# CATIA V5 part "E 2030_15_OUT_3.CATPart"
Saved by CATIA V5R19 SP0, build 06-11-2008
Material "Plastic": density 1200 kg/m3, Young's modulus 2.2e+09 Pa, Poisson ratio 0.38, thermal expansion 6.84e-05 1/K
Bounding box of the stored display mesh (mm): x 37.75 to 52.85, y -7.54 to 7.54, z -2 to 0
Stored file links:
  G:\UTB\Kombinované\Bakalářská práce\Catia\FORMA\E 2030_15_OUT_3.CATPart
  D:\Aplikace\CATIA\Nová složka\win_b64\startup\materials\Catalog.CATMaterial
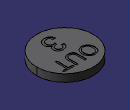
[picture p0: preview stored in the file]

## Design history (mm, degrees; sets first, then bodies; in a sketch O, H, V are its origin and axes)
Body1 "E 2030_15_OUT_1-8" (main body)
  Solid1: solid without history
